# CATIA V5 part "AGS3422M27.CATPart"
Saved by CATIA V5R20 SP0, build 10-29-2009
Part number: AGS3422M27
Definition: NONE
Nomenclature: AGS3422M27
Source: Unknown
Description: AGS3422M27
Bounding box of the stored display mesh (mm): x -39 to 45, y -37 to 37, z -37 to 37
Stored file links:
  C:\Users\Utente\Desktop\IO LAVORO\3D X SITO CF\X SITO\PLASTICA\AGS\AGS3422M27.CATPart
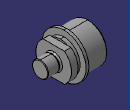
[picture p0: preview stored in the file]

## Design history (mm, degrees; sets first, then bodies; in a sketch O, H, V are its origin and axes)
Body1 "AGS3422M27" (main body)
  Solid1: solid without history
